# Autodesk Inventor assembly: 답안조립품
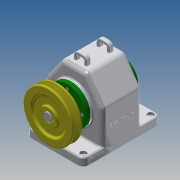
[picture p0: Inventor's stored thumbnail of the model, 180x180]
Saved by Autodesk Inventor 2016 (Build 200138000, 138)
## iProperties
Created: 2016-12
Part Number: 답안조립품
Document SubType Name: Assembly
Designer: Administrator
Author: Administrator
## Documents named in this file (15)
- D:\461207V1008_김인경\답안조립품.iam
- D:\461207V1008_김인경\본체.ipt
- D:\461207V1008_김인경\뒤커버.ipt
- D:\461207V1008_김인경\스퍼기어.ipt
- D:\461207V1008_김인경\앞커버.ipt
- D:\461207V1008_김인경\축.ipt
- D:\461207V1008_김인경\V-벨트풀리.ipt
- D:\461207V1008_김인경\멈춤나사 - M4x10.ipt
- D:\461207V1008_김인경\부시.ipt
- D:\461207V1008_김인경\오일씰 28 40 8.ipt
- D:\461207V1008_김인경\키 - 5 x 5 x 18.ipt
- D:\461207V1008_김인경\키 - 6 x 6 x 22.ipt
- D:\461207V1008_김인경\베어링 6203.ipt
- D:\461207V1008_김인경\볼트 M3 x 10.ipt
- D:\461207V1008_김인경\볼트 M3 x 8.ipt
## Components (9 placed, 3 different names)
1. V-벨트풀리:1
2. ISO 4762 M3 x 10:1
3. ISO 4762 M3 x 8:1
4. ISO 4762 M3 x 10:2
5. ISO 4762 M3 x 8:2
6. ISO 4762 M3 x 10:3
7. ISO 4762 M3 x 8:3
8. ISO 4762 M3 x 10:4
9. ISO 4762 M3 x 8:4
